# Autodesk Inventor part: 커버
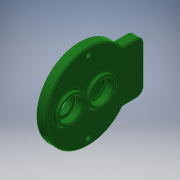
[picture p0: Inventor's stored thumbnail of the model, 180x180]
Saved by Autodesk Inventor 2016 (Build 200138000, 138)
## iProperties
Created: 2016-02
Part Number: 커버
Material: 알루미늄 6061
Document SubType Name: Modeling
Designer: mduedu
Density: 2.71 g/cm^3
Mass: 157.248 g
Surface Area: 178.476 cm^2
Volume: 58.0249 cm^3
Appearance: 매끄러움 - 짙은 산림 녹색
Author: mduedu
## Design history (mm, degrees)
sketch "스케치1"
  geometry: C1 r 43 at (0, 0); 1 further point
  constraints: 1 centre point, 1 coincident
  dimensions: "d0" = 86 diameter of C1
extrude "돌출1" new body sketch "스케치1" distance "d1" = 9; taper "d2" = 0 deg
sketch "스케치2"
  geometry: C1 r 14 at (0, 11); 1 further point
  constraints: 1 centre point, 1 vertical alignment
  dimensions: "d3" = 28 diameter of C1; "d6" = 11 distance of C1.centre point (0, 0)
extrude "돌출2" join sketch "스케치2" distance "d7" = 3; taper "d8" = 0 deg
sketch "스케치3"
  geometry: C1 r 14 at (0, -20); 1 further point
  constraints: 1 centre point, 1 vertical alignment
  dimensions: "d9" = 28 diameter of C1; "d10" = 20 distance of C1.centre point (0, 0)
extrude "돌출3" join sketch "스케치3" distance "d11" = 3; taper "d12" = 0 deg
hole "구멍1" diameter "d15" = 22; stored, may be unused: countersink angle "d19" = 90 deg, drill point angle "d21" = 0 deg; dims "d13" = 10, "d14" = 10, "d16" = 6, "d17" = 4, "d18" = 2, "d20" = 7
hole "구멍2" diameter "d24" = 18; stored, may be unused: countersink angle "d28" = 90 deg, drill point angle "d30" = 0 deg; dims "d22" = 10, "d23" = 10, "d25" = 6, "d26" = 4, "d27" = 2, "d29" = 1
hole "구멍3" diameter "d33" = 22; stored, may be unused: countersink angle "d37" = 90 deg, drill point angle "d39" = 0 deg; dims "d34" = 6, "d35" = 4, "d36" = 2, "d38" = 7, "d73" = 10, "d74" = 10
sketch "스케치7"
  geometry: L1 (-26, 34.249)-(26, 34.249); L2 (26, 34.249)-(26, 56); L3 (26, 56)-(-26, 56); L4 (-26, 56)-(-26, 34.249); A1 r 43 centre (0, 0) between (-26, 34.249) and (26, 34.249) reference; 1 further point
  constraints: 8 end point, 2 parallel, 2 point on circle, 1 horizontal, 1 perpendicular
  dimensions: "d95" = 52 distance of L2.end L3.end; "d97" = 56 distance from line of L3 point (0, 0)
extrude "돌출5" join sketch "스케치7" stored distance "d98" = 10; taper "d99" = 0 deg
sketch "스케치4"
  geometry: C1 r 14 at (0, -20) reference; C2 r 18 at (0, -20); 1 further point
  constraints: 1 centre point, 1 coincident
  dimensions: "d40" = 36 diameter of C2
extrude "돌출4" join sketch "스케치4" distance "d41" = 4; taper "d42" = 0 deg
hole "구멍4" diameter "d45" = 22; stored, may be unused: countersink angle "d49" = 90 deg, drill point angle "d51" = 0 deg; dims "d43" = 10, "d44" = 10, "d46" = 6, "d47" = 4, "d48" = 2, "d50" = 7
hole "구멍5" diameter "d54" = 15; stored, may be unused: countersink angle "d58" = 90 deg, drill point angle "d60" = 0 deg; dims "d52" = 10, "d53" = 10, "d55" = 6, "d56" = 4, "d57" = 2, "d59" = 7
fillet "모깎기1" dims "d61" = 0.3
fillet "모깎기2" dims "d62" = 2
chamfer "모따기1" distance "d63" = 1; stored, may be unused: second distance "d64" = 2, angle "d65" = 45 deg
fillet "모깎기6" dims "d88" = 2
sketch "스케치5" dims "d67" = 72
  geometry: 4 further points
  constraints: 2 horizontal alignment, 1 coincident, 5 other
  dimensions: "d71" = 360 deg dimension on point (0, 0) point (-36, 0) (derived)
fillet "모깎기4" dims "d75" = 2
sketch "스케치6"
  geometry: 2 further points
hole "구멍6" sketch "스케치6" at (36, 0), (-36, 0) diameter "d76" = 4.5; stored, may be unused: countersink angle "d80" = 90 deg, drill point angle "d82" = 0 deg; dims "d77" = 6, "d78" = 8, "d79" = 4.6, "d81" = 8
fillet "모깎기7" dims "d100" = 8, "d101" = 2
chamfer "모따기2" distance "d90" = 1; stored, may be unused: second distance "d91" = 2, angle "d92" = 45 deg
node "솔리드1"
node "절단 모서리 투영1"
